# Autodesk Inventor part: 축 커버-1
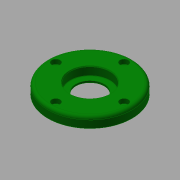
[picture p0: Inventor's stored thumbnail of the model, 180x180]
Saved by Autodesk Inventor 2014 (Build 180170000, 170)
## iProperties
Created: 2015-10
Part Number: 축 커버-1
Document SubType Name: Modeling
Designer: mdu
Density: 1 g/cm^3
Material: 강철, 연강
Appearance: 진녹색
Author: mdu
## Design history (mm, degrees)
sketch "스케치1"
  geometry: C1 r 40 at (0, 0) reference; C2 r 26 at (0, 0) reference; 1 further point
  node "참조1"
  node "참조2"
extrude "돌출1" new body sketch "스케치1" distance "d0" = 10; taper "d1" = 0 deg
extrude "돌출2" join sketch "스케치1" distance "d2" = 3; taper "d3" = 0 deg
hole "구멍1" diameter "d6" = 27; stored, may be unused: countersink angle "d10" = 90 deg, drill point angle "d12" = 118 deg; dims "d7" = 6, "d8" = 38, "d9" = 8.3, "d11" = 8, "d31" = 10, "d32" = 10
sketch "스케치2"
  geometry: C1 r 20 at (0, 0); 1 further point
  constraints: 1 centre point, 1 coincident
  dimensions: "d13" = 40 diameter of C1
extrude "돌출3" cut sketch "스케치2" distance "d14" = 3; taper "d15" = 0 deg
sketch "스케치3"
  geometry: C1 r 1.621 at (0, 32.5) reference; 1 further point
hole "구멍2" sketch "스케치3" at (0, 32.5) diameter "d16" = 4.5; stored, may be unused: countersink angle "d20" = 90 deg, drill point angle "d22" = 118 deg; dims "d17" = 6, "d18" = 8, "d19" = 4.4, "d21" = 8
fillet "모깎기1" dims "d26" = 3, "d27" = 0.3
chamfer "모따기1" distance "d28" = 1; stored, may be unused: second distance "d29" = 2, angle "d30" = 45 deg
chamfer "모따기2" distance "d33" = 0.8; stored, may be unused: second distance "d34" = 2, angle "d35" = 30 deg
node "솔리드1"
pattern_circular "원형 패턴1" dims angle "d24" = 360 deg
node "참조3"
